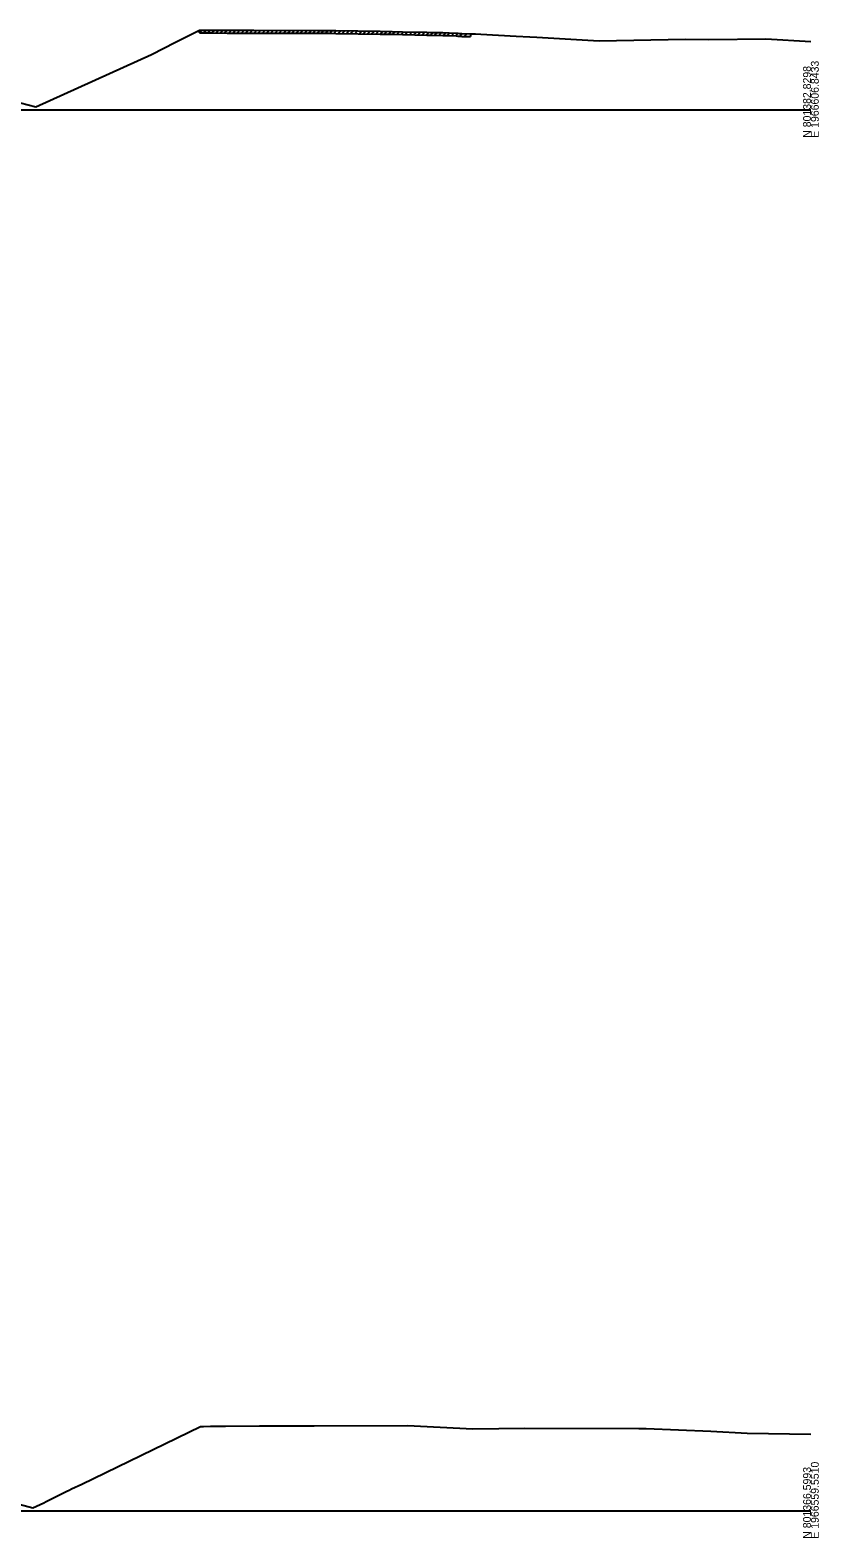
# Model space of a CAD drawing. Extents: x -4026 to 9638, y -10 to 19609.
# Drawn here: x 4421 to 4703, y 1490 to 2028 of the extents above; entities that cross this region are included whole.
import ezdxf

# ---------------------------------------------------------------- set-up
doc = ezdxf.new("R2010")
doc.units = 0
for name, color, linetype in [('RD_GPK_XS_Cell', 7, 'Continuous'), ('RD_XS_ExGround', 7, 'Continuous'), ('RD_XS_ExPaveRet', 7, 'Continuous')]:
    doc.layers.add(name, color=color, linetype=linetype)

msp = doc.modelspace()

# ---------------------------------------------------------------- linework, layer by layer
at = {"layer": 'RD_GPK_XS_Cell'}
for p, q in [((4350, 2000), (4700, 2000)), ((4350, 1500), (4700, 1500))]:
    msp.add_line(p, q, dxfattribs=at)
at = {"layer": 'RD_XS_ExGround'}
for points in [[(4417.76, 2002.41), (4423.3, 2000.98), (4464.62, 2019.75), (4473.1, 2024.11), (4481.66, 2028.4), (4485.5, 2028.4), (4486.01, 2028.4), (4491.56, 2028.38), (4495.06, 2028.37), (4501.07, 2028.37), (4523.95, 2028.3), (4526.83, 2028.28), (4527.89, 2028.27), (4530.42, 2028.23), (4546.23, 2027.99), (4550.55, 2027.91), (4554.13, 2027.85), (4562.89, 2027.65), (4564.15, 2027.62), (4568.59, 2027.51), (4570.81, 2027.45), (4573.35, 2027.37), (4573.93, 2027.29), (4574.39, 2027.22), (4575.37, 2027.19), (4578.51, 2027.09), (4580.31, 2027.03), (4582.11, 2026.91), (4594.73, 2026.26), (4599.67, 2025.99), (4602.19, 2025.9), (4624.41, 2024.57), (4655.25, 2025.17), (4663.58, 2025.06), (4683.86, 2025.33), (4700, 2024.33)], [(4413.81, 1503.22), (4422.23, 1501.06), (4426.15, 1502.84), (4426.96, 1503.26), (4428.18, 1503.87), (4430.01, 1504.79), (4434.36, 1506.95), (4435.2, 1507.36), (4435.98, 1507.75), (4439.7, 1509.41), (4482.09, 1530.02), (4483.17, 1530.03), (4485.69, 1530.12), (4486.02, 1530.13), (4486.8, 1530.12), (4491.02, 1530.11), (4503.17, 1530.31), (4503.49, 1530.32), (4503.86, 1530.33), (4522.71, 1530.31), (4555.95, 1530.37), (4579.3, 1529.27), (4597.85, 1529.46), (4638.54, 1529.36), (4641.23, 1529.32), (4664.28, 1528.35), (4677.3, 1527.68), (4700, 1527.32)]]:
    msp.add_lwpolyline(points, dxfattribs=at)
at = {"layer": 'RD_XS_ExPaveRet'}
for p, q in [((4481.67, 2027.4), (4482.67, 2028.4)), ((4481.67, 2027.4), (4481.67, 2028.4)), ((4481.67, 2027.4), (4485.5, 2027.4)), ((4483.17, 2027.4), (4484.17, 2028.4)), ((4484.67, 2027.4), (4485.67, 2028.4)), ((4485.5, 2027.4), (4486.01, 2027.4)), ((4486.01, 2027.4), (4491.56, 2027.38)), ((4486.17, 2027.4), (4487.16, 2028.4)), ((4487.67, 2027.39), (4488.66, 2028.39)), ((4489.17, 2027.39), (4490.16, 2028.39)), ((4490.67, 2027.39), (4491.66, 2028.38)), ((4491.56, 2027.38), (4495.06, 2027.37)), ((4492.17, 2027.38), (4493.16, 2028.38)), ((4493.67, 2027.38), (4494.66, 2028.37)), ((4495.06, 2027.37), (4501.07, 2027.37)), ((4495.17, 2027.37), (4496.17, 2028.37)), ((4496.67, 2027.37), (4497.67, 2028.37)), ((4498.17, 2027.37), (4499.17, 2028.37)), ((4499.67, 2027.37), (4500.67, 2028.37)), ((4501.07, 2027.37), (4523.95, 2027.3)), ((4501.17, 2027.37), (4502.16, 2028.36)), ((4502.67, 2027.36), (4503.66, 2028.36)), ((4504.17, 2027.36), (4505.16, 2028.36)), ((4505.67, 2027.35), (4506.66, 2028.35)), ((4507.17, 2027.35), (4508.16, 2028.35)), ((4508.67, 2027.35), (4509.66, 2028.34)), ((4510.17, 2027.34), (4511.16, 2028.34)), ((4511.67, 2027.34), (4512.66, 2028.33)), ((4513.17, 2027.33), (4514.16, 2028.33)), ((4514.67, 2027.33), (4515.66, 2028.33)), ((4516.17, 2027.32), (4517.16, 2028.32)), ((4517.67, 2027.32), (4518.66, 2028.32)), ((4519.17, 2027.31), (4520.16, 2028.31)), ((4520.67, 2027.31), (4521.66, 2028.31)), ((4522.17, 2027.31), (4523.16, 2028.3)), ((4523.67, 2027.3), (4524.66, 2028.3)), ((4523.95, 2027.3), (4526.83, 2027.28)), ((4525.17, 2027.29), (4526.16, 2028.29)), ((4526.67, 2027.28), (4527.65, 2028.27)), ((4526.83, 2027.28), (4527.89, 2027.27)), ((4527.89, 2027.27), (4530.42, 2027.23)), ((4528.17, 2027.26), (4529.15, 2028.25)), ((4529.67, 2027.24), (4530.65, 2028.22)), ((4530.42, 2027.23), (4546.23, 2026.99)), ((4531.17, 2027.22), (4532.15, 2028.2)), ((4532.67, 2027.19), (4533.65, 2028.18)), ((4534.17, 2027.17), (4535.15, 2028.16)), ((4535.67, 2027.15), (4536.65, 2028.13)), ((4537.17, 2027.13), (4538.15, 2028.11)), ((4538.67, 2027.1), (4539.65, 2028.09)), ((4540.17, 2027.08), (4541.15, 2028.07)), ((4541.67, 2027.06), (4542.65, 2028.05)), ((4543.17, 2027.04), (4544.15, 2028.02)), ((4544.67, 2027.02), (4545.65, 2028)), ((4546.17, 2026.99), (4547.15, 2027.98)), ((4546.23, 2026.99), (4550.55, 2026.91)), ((4547.67, 2026.97), (4548.65, 2027.95)), ((4549.17, 2026.94), (4550.15, 2027.92)), ((4550.55, 2026.91), (4554.13, 2026.85)), ((4550.67, 2026.91), (4551.65, 2027.89)), ((4552.17, 2026.88), (4553.15, 2027.87)), ((4553.67, 2026.86), (4554.65, 2027.84)), ((4554.13, 2026.85), (4562.89, 2026.65)), ((4555.17, 2026.83), (4556.14, 2027.81)), ((4556.67, 2026.79), (4557.64, 2027.77)), ((4558.17, 2026.76), (4559.14, 2027.74)), ((4559.67, 2026.72), (4560.64, 2027.7)), ((4561.17, 2026.69), (4562.14, 2027.67)), ((4562.67, 2026.65), (4563.65, 2027.63)), ((4562.89, 2026.65), (4564.15, 2026.62)), ((4564.15, 2026.62), (4568.59, 2026.51)), ((4564.17, 2026.62), (4565.14, 2027.6)), ((4565.67, 2026.59), (4566.64, 2027.56)), ((4567.17, 2026.55), (4568.14, 2027.52)), ((4568.59, 2026.51), (4570.81, 2026.45)), ((4568.67, 2026.51), (4569.64, 2027.48)), ((4570.17, 2026.47), (4571.14, 2027.44)), ((4570.81, 2026.45), (4573.35, 2026.37)), ((4571.67, 2026.42), (4572.63, 2027.39)), ((4573.17, 2026.37), (4574.06, 2027.27)), ((4573.35, 2026.37), (4573.93, 2026.29)), ((4573.93, 2026.29), (4574.39, 2026.22)), ((4574.39, 2026.22), (4575.37, 2026.19)), ((4574.67, 2026.21), (4575.64, 2027.18)), ((4575.37, 2026.19), (4578.51, 2026.09)), ((4576.17, 2026.16), (4577.14, 2027.13)), ((4578.51, 2027.09), (4578.51, 2026.09))]:
    msp.add_line(p, q, dxfattribs=at)

# ---------------------------------------------------------------- texts
at = {"layer": 'RD_GPK_XS_Cell'}
for s, p in [('N 801382.8298', (4700, 1990)), ('E 1966606.8433', (4702.8, 1990)), ('N 801366.5993', (4700, 1490)), ('E 1966559.5510', (4702.8, 1490))]:
    msp.add_text(s, height=2.8, rotation=90, dxfattribs=at).set_placement(p)

doc.saveas('drawing.dxf')
